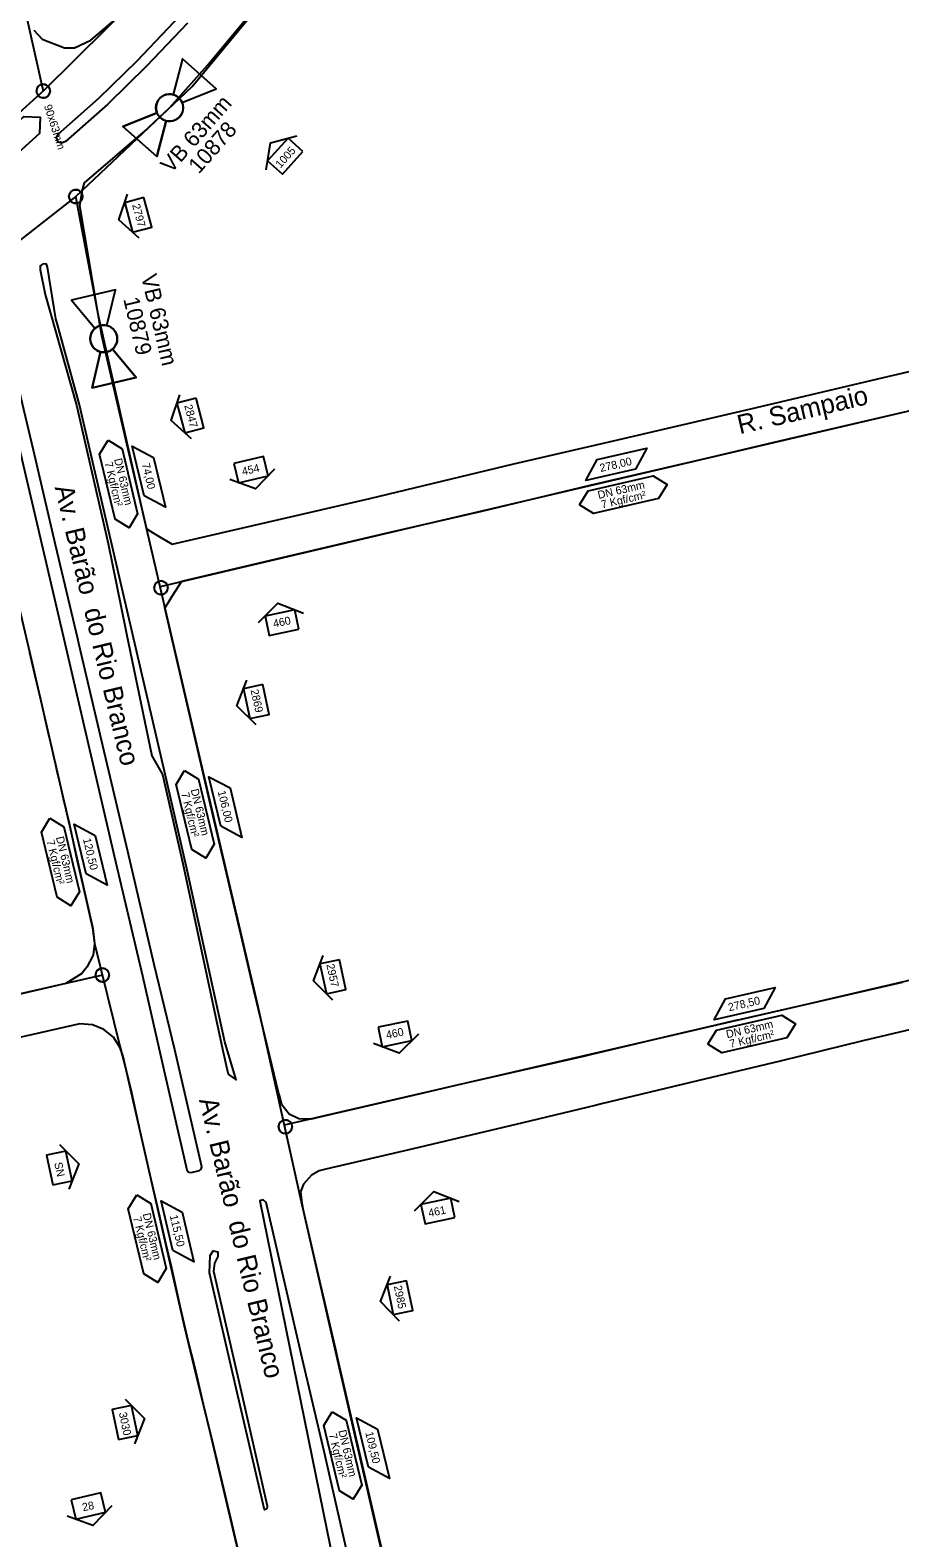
# Model space of a CAD drawing. Extents: x 656692 to 673945, y 7585994 to 7599066.
# Drawn here: x 670454 to 670782, y 7592467 to 7593036 of the extents above; entities that cross this region are included whole.
import ezdxf

# ---------------------------------------------------------------- set-up
doc = ezdxf.new("R2010")
doc.units = 0
for name, color, linetype in [('FORMATO', 7, 'Continuous'), ('LOGRADOURO', 7, 'Continuous'), ('LOGRADOURO_TEXTO', 7, 'Continuous'), ('NUM_REF', 7, 'Continuous'), ('SIMBOLO', 7, 'Continuous'), ('TEXTO', 7, 'Continuous'), ('TUBO_PEAD_GN_63', 7, 'Continuous'), ('TUBO_PEAD_GN_90', 7, 'Continuous'), ('VALVULA_PEAD_63', 7, 'Continuous')]:
    doc.layers.add(name, color=color, linetype=linetype)

# ---------------------------------------------------------------- blocks, each defined once
blk = doc.blocks.new('INTERLIGACAO_5')
at = {"layer": 'SIMBOLO'}
blk.add_circle((0, 0), 1.28, dxfattribs=at)
for start, end in [(0, 180), (180, 0)]:
    blk.add_arc((0, 0), 1.28, start, end, dxfattribs=at)
blk = doc.blocks.new('VALVULA_PEAD_DN_9')
at = {"layer": 'VALVULA_PEAD_63'}
for points in [[(-1.14, 0.57), (-4.25, 2.13), (-4.25, -2.13), (-1.14, -0.57)], [(-1.14, -0.57), (-4.25, -2.13), (-4.25, 2.13), (-1.14, 0.57)], [(1.14, -0.57), (4.25, -2.13), (4.25, 2.13), (1.14, 0.57)], [(1.14, -0.57), (4.25, -2.13), (4.25, 2.13), (1.14, 0.57)]]:
    blk.add_lwpolyline(points, dxfattribs=at)
blk.add_circle((0, 0), 1.28, dxfattribs=at)
for start, end in [(90, 270), (153.4349, 206.5651), (270, 90), (0, 26.5651), (333.4349, 0)]:
    blk.add_arc((0, 0), 1.28, start, end, dxfattribs=at)
blk = doc.blocks.new('NUM_REF_1')
at = {"layer": 'NUM_REF'}
blk.add_lwpolyline([(-4.3125, 0.9375), (0, 3.75), (4.3125, 0.9375)], dxfattribs=at)
blk.add_lwpolyline([(2.875, -1.875), (2.875, 1.875), (-2.875, 1.875), (-2.875, -1.875)], close=True, dxfattribs=at)

msp = doc.modelspace()

# ---------------------------------------------------------------- linework, layer by layer
at = {"layer": 'LOGRADOURO'}
for points in [[(670472.49, 7592969.95), (670473.46, 7592975.88), (670474.22, 7592978.5), (670496.48, 7592997.68), (670506.31, 7593006.87), (670520.71, 7593023), (670539.44, 7593045.63), (670562.52, 7593077.68), (670585.9, 7593110.7), (670633, 7593177.03), (670657.07, 7593210.84), (670688.65, 7593255.22), (670710.26, 7593285.77), (670762.8, 7593359.97)], [(670455.1, 7593036.14), (670458.23, 7593032.8), (670466.61, 7593029.41), (670470.38, 7593029.52), (670476.62, 7593032.41), (670489.16, 7593043.05)], [(670513.07, 7593038.76), (670497.63, 7593022.5), (670482.99, 7593008.18), (670467.05, 7592994.06), (670465.47, 7592993.47), (670464.23, 7592993.92), (670463.64, 7592995.6), (670464.32, 7592996.91), (670479.64, 7593010.49), (670494.13, 7593024.56), (670510.38, 7593041.76)], [(670497.81, 7592847.8), (670499.81, 7592846.59), (670502.44, 7592845.09), (670507.34, 7592842.19), (670581.94, 7592859.41), (670636.27, 7592872.44), (670673.89, 7592881.18), (670727.81, 7592893.77), (670775.73, 7592905), (670815.83, 7592914.36), (670868.12, 7592926.68), (670954.57, 7592947.04), (671011.28, 7592960.26), (671028.95, 7592964.51), (671033.56, 7592966.31), (671035.77, 7592967.92), (671038.72, 7592971.06), (671040.8, 7592975.53), (671041.39, 7592978.38), (671040.8, 7592983.57), (671027.32, 7593039.62)], [(670497.79, 7592847.78), (670490.22, 7592879.98), (670480.81, 7592920.76), (670472.49, 7592969.95)], [(670463.4, 7592927.2), (670460.24, 7592946.74), (670459.87, 7592947.77), (670458.59, 7592947.99), (670457.46, 7592947.21), (670457.43, 7592945.74), (670459.41, 7592936.33), (670471.14, 7592894.57), (670477.92, 7592864.87), (670483.09, 7592842.45), (670489.71, 7592810.21), (670490.03, 7592808.31), (670499.6, 7592762.26), (670503.63, 7592755.15), (670511.38, 7592721.62), (670526.27, 7592651.54), (670528.28, 7592642.57), (670528.91, 7592641.72), (670531.47, 7592639.91), (670527.16, 7592654.32), (670512.74, 7592720.18), (670504.61, 7592755.27), (670489.05, 7592822.49), (670479.33, 7592864.3), (670472.38, 7592894.74), (670464.05, 7592925.01), (670463.41, 7592927.21)], [(670463.29, 7592841.88), (670454.91, 7592877.59), (670444.75, 7592920.48)], [(670445.44, 7592896.25), (670456.22, 7592850.07), (670467.25, 7592802.62), (670485.39, 7592724.53), (670496.04, 7592679.17), (670504.18, 7592643.67), (670512.87, 7592605.99), (670513.48, 7592605.15), (670514.5, 7592605.01), (670517.6, 7592605.7), (670518.28, 7592606.24), (670518.51, 7592607.14), (670508.66, 7592649.7), (670508.31, 7592651.28), (670500.55, 7592683.46), (670490.51, 7592726.09), (670481.13, 7592766.03), (670472.03, 7592804.6), (670471.65, 7592806.37), (670463.29, 7592841.88)], [(670817.87, 7592899.99), (670780.93, 7592891.36), (670736.58, 7592880.96), (670708.32, 7592874.38), (670664.97, 7592864.25), (670624.07, 7592854.52), (670587.83, 7592846.14), (670537.97, 7592834.5), (670510.87, 7592827.99), (670507.13, 7592822.38), (670505.72, 7592819.89), (670504.55, 7592818.12)], [(670446.26, 7592832.11), (670454.04, 7592798.88), (670468.59, 7592735.92), (670477.3, 7592697.03), (670478.01, 7592691.36), (670477.52, 7592686.97), (670475.13, 7592682.46), (670473.15, 7592680.1), (670467.18, 7592676.33), (670431.32, 7592668.04)], [(670720.53, 7592662.42), (670703.89, 7592658.57), (670702.16, 7592658.17), (670665.59, 7592649.54), (670663.05, 7592648.89), (670615.37, 7592638.01), (670596.66, 7592633.61), (670562.39, 7592625.72), (670559.82, 7592625.16), (670555.16, 7592625.21), (670551.46, 7592627.04), (670548.67, 7592630.47), (670547.9, 7592633.61), (670547.41, 7592635.12), (670538.3, 7592673.24), (670533.77, 7592692.74), (670523.08, 7592738.29), (670504.55, 7592818.12)], [(671166.42, 7592461.1), (671158.68, 7592493.21), (671156.55, 7592502.04), (671152.05, 7592521.15), (671143.39, 7592556.93), (671126.9, 7592625.64), (671115.66, 7592672.62), (671104.79, 7592718.29), (671103.14, 7592722.95), (671100.84, 7592725.98), (671095.16, 7592729.32), (671090.23, 7592729.88), (671081.5, 7592728.06), (671015.02, 7592712.68), (670991.78, 7592707.11), (670959.18, 7592699.54), (670920.7, 7592690.84), (670852.27, 7592674.86), (670795.2, 7592661.05), (670768, 7592654.72), (670736.72, 7592647.03), (670705.51, 7592639.52)], [(670720.53, 7592662.42), (670782.89, 7592676.84)], [(670532.26, 7592462.05), (670521.75, 7592506.49), (670518, 7592522), (670517.42, 7592524.41), (670511.87, 7592547.48), (670502.41, 7592589.06), (670488.78, 7592648.75), (670487.69, 7592652.09), (670485.16, 7592656.08), (670481.53, 7592659.01), (670477.28, 7592660.7), (670472.46, 7592661.11), (670419.11, 7592649.03)], [(670705.51, 7592639.52), (670669.38, 7592630.95), (670666.9, 7592630.33), (670639.62, 7592623.77), (670598.3, 7592613.94), (670565.23, 7592606.21), (670562.75, 7592605.55), (670559.94, 7592604.01), (670556.9, 7592600.53), (670555.7, 7592597.73), (670556.22, 7592593.35), (670556.79, 7592590.82), (670562.01, 7592567.81), (670569.01, 7592537.62), (670569.58, 7592535.29), (670578.23, 7592497.75), (670599.49, 7592405.73)], [(670602.69, 7592310.54), (670603.25, 7592309.78), (670604.17, 7592309.68), (670606.93, 7592310.28), (670607.65, 7592310.73), (670608.03, 7592311.84), (670596.48, 7592361.78), (670583.46, 7592417.89), (670583.33, 7592419.65), (670576.37, 7592448.23), (670564.69, 7592499.65), (670556.35, 7592534.94), (670542.74, 7592593.67), (670541.63, 7592594.66), (670540.39, 7592594.31), (670568.38, 7592456.47), (670577.1, 7592420.13), (670602.69, 7592310.54)], [(670543, 7592478.09), (670542.16, 7592477.61), (670531.75, 7592522.42), (670521.4, 7592567.11), (670521.62, 7592573.62), (670522.75, 7592575.45), (670524.54, 7592575), (670524.59, 7592573.24), (670523.25, 7592570.71), (670522.86, 7592567.69), (670533.66, 7592520.67), (670543.18, 7592479.2), (670543, 7592478.09)], [(670628.17, 7592320), (670623.09, 7592320.68), (670619.41, 7592323.54), (670617.72, 7592327.93), (670606.3, 7592376.62), (670599.49, 7592405.73), (670578.23, 7592497.75), (670569.58, 7592535.29)]]:
    msp.add_lwpolyline(points, dxfattribs=at)
at = {"layer": 'SIMBOLO'}
for points in [[(670432.23, 7592980.51), (670432.55, 7592986.68), (670451.3, 7593003.6), (670457.48, 7593003.28), (670457.16, 7592997.1), (670438.41, 7592980.19), (670432.23, 7592980.51)], [(670483.09, 7592881.41), (670488.37, 7592878.18), (670494.27, 7592853.63), (670491.04, 7592848.36), (670485.77, 7592851.59), (670479.86, 7592876.14), (670483.09, 7592881.41)], [(670661.02, 7592856.99), (670664.29, 7592862.24), (670688.9, 7592867.92), (670694.14, 7592864.64), (670690.87, 7592859.39), (670666.26, 7592853.71), (670661.02, 7592856.99)], [(670512.01, 7592756.67), (670517.29, 7592753.44), (670523.19, 7592728.89), (670519.96, 7592723.62), (670514.69, 7592726.85), (670508.78, 7592751.4), (670512.01, 7592756.67)], [(670461.16, 7592738.72), (670466.43, 7592735.49), (670472.34, 7592710.93), (670469.11, 7592705.66), (670463.83, 7592708.89), (670457.92, 7592733.44), (670461.16, 7592738.72)], [(670709.47, 7592653.44), (670712.75, 7592658.69), (670737.36, 7592664.37), (670742.6, 7592661.09), (670739.33, 7592655.84), (670714.72, 7592650.16), (670709.47, 7592653.44)], [(670493.91, 7592596.55), (670499.18, 7592593.32), (670505.09, 7592568.77), (670501.86, 7592563.49), (670496.58, 7592566.72), (670490.68, 7592591.27), (670493.91, 7592596.55)], [(670567.72, 7592514.7), (670572.99, 7592511.47), (670578.9, 7592486.92), (670575.67, 7592481.65), (670570.39, 7592484.88), (670564.48, 7592509.43), (670567.72, 7592514.7)]]:
    msp.add_lwpolyline(points, dxfattribs=at)
for points in [[(670496.76, 7592860.42), (670492.26, 7592879.1), (670500.23, 7592874.85), (670504.72, 7592856.16)], [(670682.14, 7592870.46), (670663.41, 7592866.14), (670667.74, 7592874.07), (670686.47, 7592878.39)], [(670525.68, 7592735.68), (670521.18, 7592754.36), (670529.15, 7592750.11), (670533.64, 7592731.42)], [(670474.82, 7592717.72), (670470.32, 7592736.41), (670478.29, 7592732.15), (670482.78, 7592713.46)], [(670730.6, 7592666.91), (670711.87, 7592662.59), (670716.2, 7592670.51), (670734.92, 7592674.84)], [(670507.57, 7592575.55), (670503.08, 7592594.24), (670511.04, 7592589.98), (670515.53, 7592571.3)], [(670581.38, 7592493.71), (670576.88, 7592512.39), (670584.85, 7592508.14), (670589.34, 7592489.45)]]:
    msp.add_lwpolyline(points, close=True, dxfattribs=at)
at = {"layer": 'TUBO_PEAD_GN_63'}
msp.add_line((670470.89, 7592973.34), (670411.47, 7592926.8), dxfattribs=at)
for points in [[(670270.63, 7593828.18), (670395.17, 7593291.1), (670412.62, 7593214.31), (670425.77, 7593159.21), (670458.65, 7593013.14)], [(670470.91, 7592973.35), (670514.84, 7593014.82), (670541.39, 7593046.9), (670643.42, 7593190.44), (670755.95, 7593349.63), (670855.77, 7593490.31)], [(670618.18, 7592329.04), (670601.37, 7592398.3), (670584.95, 7592468.34), (670570.07, 7592532.72), (670555.71, 7592595.58), (670539.55, 7592668.66), (670518.27, 7592759.46), (670496.46, 7592853.09), (670479.53, 7592928.27), (670470.91, 7592973.35)], [(671027.78, 7592949.1), (671009, 7592944.76), (670994.66, 7592941.36), (670977.27, 7592937.32), (670964.28, 7592934.28), (670953.45, 7592931.76), (670947.94, 7592930.46), (670942.87, 7592929.27), (670938.05, 7592928.13), (670932.31, 7592926.79), (670931.23, 7592926.54), (670930.08, 7592926.26), (670929.13, 7592926.04), (670928.08, 7592925.8), (670927.69, 7592925.7), (670927.32, 7592925.62), (670926.5, 7592925.43), (670925.97, 7592925.3), (670596.71, 7592848.17), (670502.75, 7592826.09)], [(670453.49, 7592801.28), (670455.36, 7592793.06), (670457.56, 7592783.66), (670459.51, 7592775.15), (670460.38, 7592771.32), (670461.13, 7592768.18), (670461.73, 7592765.67), (670462.41, 7592762.66), (670463.21, 7592759.01), (670463.94, 7592755.85), (670464.62, 7592752.99), (670465.55, 7592749.07), (670466.34, 7592745.47), (670467.12, 7592742.17), (670467.69, 7592739.73), (670468.37, 7592736.78), (670469.96, 7592729.74), (670471.49, 7592722.64), (670473.11, 7592715.62), (670474.92, 7592707.39), (670476.45, 7592700.59), (670477.18, 7592697.27), (670477.59, 7592694.43), (670478.04, 7592691.47), (670487.62, 7592652.19), (670489.79, 7592644.03), (670491.9, 7592635.17), (670495.03, 7592620.74), (670499.3, 7592602.45), (670502.48, 7592588.46), (670504.84, 7592578.46), (670507.02, 7592568.97), (670510.19, 7592554.63), (670513.23, 7592541.56), (670515.69, 7592531.79), (670518.95, 7592517.59), (670522.86, 7592501.61), (670526.63, 7592485.77), (670529.81, 7592472.37), (670532.22, 7592462.1)], [(671112.99, 7592753.42), (671059.25, 7592741.34), (671038.66, 7592736.48), (670980.45, 7592722.84), (670959.64, 7592718.12), (670939.01, 7592713.29), (670917.52, 7592708.19), (670902.91, 7592704.76), (670889.5, 7592701.67), (670878.15, 7592699.09), (670867.67, 7592696.68), (670857.06, 7592694.2), (670745.58, 7592668.14), (670720.29, 7592662.4), (670698.1, 7592657.18), (670549.6, 7592622.83)], [(670480.96, 7592679.5), (670442.92, 7592670.73)]]:
    msp.add_lwpolyline(points, dxfattribs=at)
at = {"layer": 'TUBO_PEAD_GN_90'}
msp.add_line((670458.89, 7593013.38), (670508.2, 7593062.25), dxfattribs=at)
msp.add_lwpolyline([(670458.98, 7593013.47), (670404.86, 7592964.46), (670397.28, 7592960.88)], dxfattribs=at)

# ---------------------------------------------------------------- block references
at = {"layer": 'FORMATO'}
for p, xscale, yscale, rotation in [((670549.97, 7592988.54), 2, 2, 47.927921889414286), ((670494.47, 7592966.41), 2, 2.0000000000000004, 104.79500604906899), ((670514.21, 7592890.7), 2, 2.0000000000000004, 104.79500604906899), ((670537.05, 7592870.31), 2, 2.0000000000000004, -166.66750398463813), ((670548.76, 7592812.47), 2, 2, 11.962463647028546), ((670539.07, 7592782.73), 1.9999999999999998, 2.0000000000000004, 102.20390244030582), ((670567.97, 7592678.87), 1.9999999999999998, 2.0000000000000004, 102.20390244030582), ((670591.39, 7592657.3), 2, 2, -168.0566481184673), ((670464.72, 7592606.69), 2, 2, -78.08582592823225), ((670607.6, 7592590.44), 2, 2, 11.962463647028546), ((670593.26, 7592557.73), 2, 2, 101.48298339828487), ((670489.48, 7592510.63), 2, 2, -78.08582592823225), ((670475.65, 7592479.05), 2, 2.0000000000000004, -166.66750398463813)]:
    msp.add_blockref('NUM_REF_1', p, dxfattribs=dict(at, xscale=xscale, yscale=yscale, rotation=rotation))
at = {"layer": 'SIMBOLO', "xscale": 2, "yscale": 2}
for p, rotation in [((670458.65, 7593013.14), -72.2245311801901), ((670470.91, 7592973.35), -14.764722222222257), ((670503.07, 7592825.68), -14.764722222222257), ((670480.96, 7592679.5), -14.764722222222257), ((670550.03, 7592622.24), -14.764722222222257)]:
    msp.add_blockref('INTERLIGACAO_5', p, dxfattribs=dict(at, rotation=rotation))
at = {"layer": 'VALVULA_PEAD_63', "xscale": 4.000000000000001, "yscale": 4.000000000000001}
for p, rotation in [((670506.31, 7593006.87), 48.588511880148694), ((670481.47, 7592919.67), 103.30522659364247)]:
    msp.add_blockref('VALVULA_PEAD_DN_9', p, dxfattribs=dict(at, rotation=rotation))

# ---------------------------------------------------------------- texts
for s, height, rotation, p in [('VB 63mm', 6, 48.5885, (670506.88, 7592981.82)), ('  90x63mm', 3, 287.7755, (670458.19, 7593009.68)), ('10878', 6, 48.5885, (670517.35, 7592981.59)), ('1005', 3, 47.9279, (670548.16, 7592983.86)), ('2797', 3, 284.795, (670492.14, 7592970.17)), ('VB 63mm', 6, 283.3052, (670495.51, 7592943.27)), ('10879', 6, 283.3052, (670488.81, 7592934.68)), ('2847', 3, 284.795, (670511.84, 7592894.44)), ('454', 3, 13.3325, (670533.99, 7592868.05)), ('460', 3, 11.9625, (670545.71, 7592810.61)), ('2869', 3, 282.2039, (670536.88, 7592787.04)), ('2957', 3, 282.2039, (670565.48, 7592683.41)), ('460', 3, 11.9434, (670588.34, 7592655.36)), ('SN', 3, 281.9142, (670462.76, 7592608.57)), ('461', 3, 11.9625, (670604.28, 7592588.15)), ('2985', 3, 281.483, (670590.95, 7592562.06)), ('3030', 3, 281.9142, (670487.15, 7592514.22)), ('28', 3, 11.8282, (670473.67, 7592477.11))]:
    msp.add_text(s, height=height, rotation=rotation).set_placement(p)
at = {"layer": 'LOGRADOURO_TEXTO'}
for s, rotation, p in [('R. Sampaio', 13.1978, (670721.51, 7592883.61)), ('Av. Barão  do Rio Branco', 283.441, (670462.9, 7592863.6)), ('Av. Barão  do Rio Branco', 283.441, (670517.39, 7592632.38))]:
    msp.add_text(s, height=7.2, rotation=rotation, dxfattribs=at).set_placement(p)
at = {"layer": 'TEXTO'}
for s, rotation, p in [('7 Kgf/cm²', 283.5225, (670481.76, 7592872.83)), ('DN 63mm', 283.5225, (670485.35, 7592874.17)), ('74,00', 283.5225, (670495.81, 7592872.38)), ('278,00', 12.9963, (670669.03, 7592869.36)), ('DN 63mm', 12.9963, (670668.28, 7592859.18)), ('7 Kgf/cm²', 12.9963, (670669.59, 7592855.58)), ('7 Kgf/cm²', 283.5225, (670510.68, 7592748.09)), ('DN 63mm', 283.5225, (670514.27, 7592749.43)), ('106,00', 283.5225, (670524.45, 7592748.77)), ('7 Kgf/cm²', 283.5225, (670459.83, 7592730.13)), ('DN 63mm', 283.5225, (670463.41, 7592731.47)), ('120,50', 283.5225, (670473.6, 7592730.81)), ('278,50', 12.9963, (670717.49, 7592665.81)), ('DN 63mm', 12.9963, (670716.74, 7592655.63)), ('7 Kgf/cm²', 12.9963, (670718.05, 7592652.03)), ('7 Kgf/cm²', 283.5225, (670492.58, 7592587.97)), ('DN 63mm', 283.5225, (670496.16, 7592589.31)), ('115,50', 283.5225, (670506.35, 7592588.65)), ('7 Kgf/cm²', 283.5225, (670566.39, 7592506.12)), ('DN 63mm', 283.5225, (670569.97, 7592507.46)), ('109,50', 283.5225, (670580.16, 7592506.8))]:
    msp.add_text(s, height=3, rotation=rotation, dxfattribs=at).set_placement(p)

doc.saveas('drawing.dxf')
